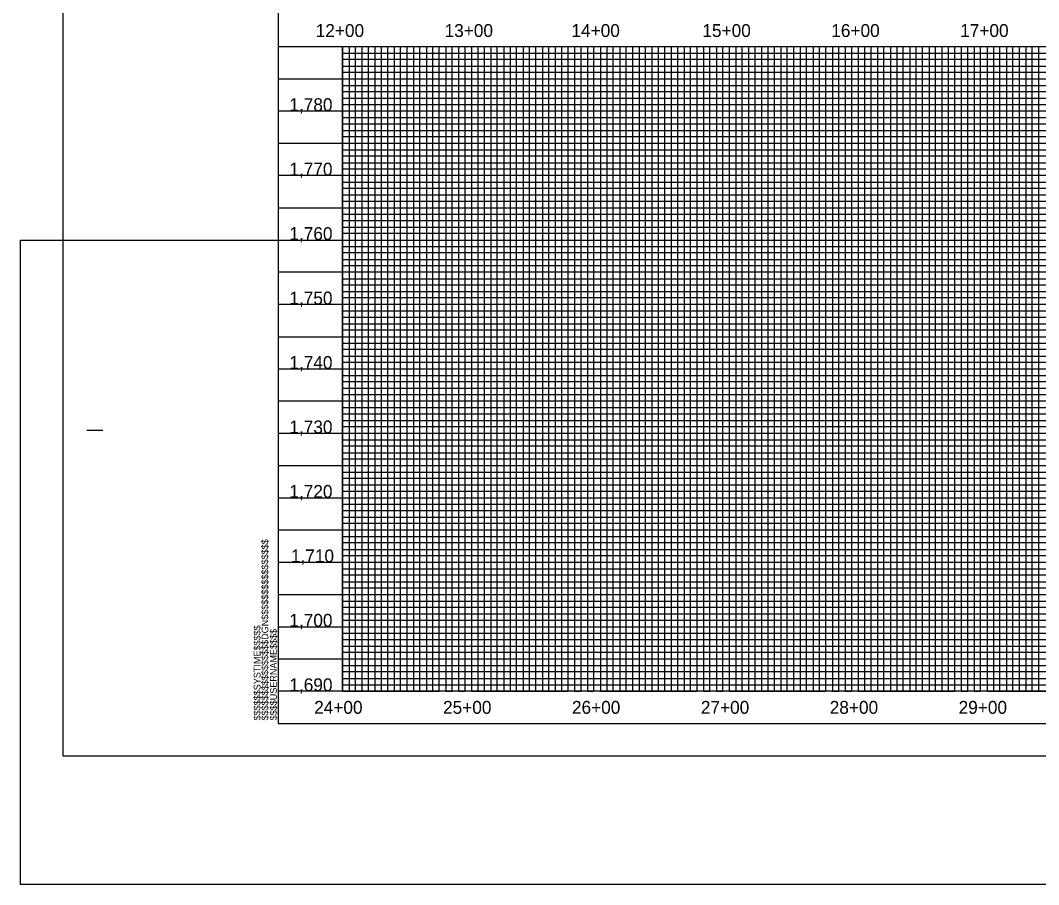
# Model space of a CAD drawing. Extents: x 505569 to 516904, y 436011 to 484484.
# Drawn here: x 505569 to 506359, y 483009 to 483679 of the extents above; entities that cross this region are included whole.
import ezdxf

# ---------------------------------------------------------------- set-up
doc = ezdxf.new("R2010")
doc.units = 0
for name, color, linetype in [('COGO Default Curve', 7, 'Continuous'), ('Exist Profile Cell', 7, 'Continuous'), ('Prop Grid Mask', 7, 'Continuous'), ('Prop Vertical Profile Curve Label', 7, 'Continuous'), ('Prop Vertical Profile Grade', 7, 'Continuous'), ('Prop Vertical Profile Grade Label', 7, 'Continuous'), ('Scratch_Level_2', 7, 'Continuous')]:
    doc.layers.add(name, color=color, linetype=linetype)

msp = doc.modelspace()

# ---------------------------------------------------------------- linework, layer by layer
at = {"layer": 'COGO Default Curve'}
for points in [[(505794.08, 483658.71), (505844.08, 483658.71), (505844.08, 483158.71), (505894.08, 483158.71), (505894.08, 483658.71), (505944.08, 483658.71), (505944.08, 483158.71), (505994.08, 483158.71), (505994.08, 483658.71), (506044.08, 483658.71), (506044.08, 483158.71), (506094.08, 483158.71), (506094.08, 483658.71), (506144.08, 483658.71), (506144.08, 483158.71), (506194.08, 483158.71), (506194.08, 483658.71), (506244.08, 483658.71), (506244.08, 483158.71), (506294.08, 483158.71), (506294.08, 483658.71), (506344.08, 483658.71), (506344.08, 483158.71), (506394.08, 483158.71)], [(505769.08, 483633.71), (507269.08, 483633.71)], [(507269.08, 483583.71), (505769.08, 483583.71), (505769.08, 483533.71), (507269.08, 483533.71)], [(507269.08, 483483.71), (505769.08, 483483.71), (505769.08, 483433.71), (507269.08, 483433.71)], [(507269.08, 483383.71), (505769.08, 483383.71), (505769.08, 483333.71), (507269.08, 483333.71)], [(507269.08, 483283.71), (505769.08, 483283.71), (505769.08, 483233.71), (507269.08, 483233.71)], [(507269.08, 483183.71), (505769.08, 483183.71)]]:
    msp.add_lwpolyline(points, dxfattribs=at)
at = {"layer": 'Prop Grid Mask'}
msp.add_lwpolyline([(505602.08, 483108.71), (507286.08, 483108.71), (507286.08, 484208.71), (505602.08, 484208.71)], close=True, dxfattribs=at)
at = {"layer": 'Prop Vertical Profile Curve Label'}
for p, q in [((505769.08, 483658.71), (507269.08, 483658.71)), ((505620.58, 483361.21), (505633.08, 483361.21)), ((507269.08, 483158.71), (505769.08, 483158.71)), ((505769.08, 483133.71), (507269.08, 483133.71)), ((505769.08, 483133.71), (505769.08, 483133.71)), ((505769.08, 483133.71), (505769.08, 483133.71)), ((505769.08, 483133.71), (505769.08, 483133.71)), ((505769.08, 483133.71), (505769.08, 483133.71)), ((505769.08, 483133.71), (505769.08, 483133.71)), ((505769.08, 483133.71), (505769.08, 483133.71)), ((505769.08, 483133.71), (505769.08, 483133.71))]:
    msp.add_line(p, q, dxfattribs=at)
msp.add_lwpolyline([(507269.08, 484183.71), (505769.08, 484183.71), (505769.08, 483133.71), (507269.08, 483133.71)], close=True, dxfattribs=at)
msp.add_lwpolyline([(505806.58, 483133.71), (505806.58, 483133.71)], dxfattribs=at)
at = {"layer": 'Prop Vertical Profile Grade'}
for points in [[(505819.08, 483658.71), (507219.08, 483658.71), (507219.08, 483158.71), (505819.08, 483158.71)], [(505569.08, 483508.71), (506969.08, 483508.71), (506969.08, 483008.71), (505569.08, 483008.71)]]:
    msp.add_lwpolyline(points, close=True, dxfattribs=at)
at = {"layer": 'Prop Vertical Profile Grade Label'}
for p, q in [((505819.08, 483653.71), (507219.08, 483653.71)), ((507219.08, 483648.71), (505819.08, 483648.71)), ((505819.08, 483643.71), (507219.08, 483643.71)), ((507219.08, 483638.71), (505819.08, 483638.71)), ((505819.08, 483628.71), (507219.08, 483628.71)), ((507219.08, 483623.71), (505819.08, 483623.71)), ((505819.08, 483618.71), (507219.08, 483618.71)), ((507219.08, 483613.71), (505819.08, 483613.71)), ((505819.08, 483603.71), (507219.08, 483603.71)), ((507219.08, 483598.71), (505819.08, 483598.71)), ((505819.08, 483593.71), (507219.08, 483593.71)), ((507219.08, 483588.71), (505819.08, 483588.71)), ((505819.08, 483578.71), (507219.08, 483578.71)), ((507219.08, 483573.71), (505819.08, 483573.71)), ((505819.08, 483568.71), (507219.08, 483568.71)), ((507219.08, 483563.71), (505819.08, 483563.71)), ((505819.08, 483553.71), (507219.08, 483553.71)), ((507219.08, 483548.71), (505819.08, 483548.71)), ((505819.08, 483543.71), (507219.08, 483543.71)), ((507219.08, 483538.71), (505819.08, 483538.71)), ((505819.08, 483528.71), (507219.08, 483528.71)), ((507219.08, 483523.71), (505819.08, 483523.71)), ((505819.08, 483518.71), (507219.08, 483518.71)), ((507219.08, 483513.71), (505819.08, 483513.71)), ((505819.08, 483503.71), (507219.08, 483503.71)), ((507219.08, 483498.71), (505819.08, 483498.71)), ((505819.08, 483493.71), (507219.08, 483493.71)), ((507219.08, 483488.71), (505819.08, 483488.71)), ((505819.08, 483478.71), (507219.08, 483478.71)), ((507219.08, 483473.71), (505819.08, 483473.71)), ((505819.08, 483468.71), (507219.08, 483468.71)), ((507219.08, 483463.71), (505819.08, 483463.86)), ((505819.08, 483453.71), (507219.08, 483453.71)), ((507219.08, 483448.71), (505819.08, 483448.71)), ((505819.08, 483443.71), (507219.08, 483443.71)), ((507219.08, 483438.71), (505819.08, 483438.71)), ((505819.08, 483428.71), (507219.08, 483428.71)), ((507219.08, 483423.71), (505819.08, 483423.71)), ((505819.08, 483418.71), (507219.08, 483418.71)), ((507219.08, 483413.71), (505819.08, 483413.71)), ((505819.08, 483403.71), (507219.08, 483403.71)), ((507219.08, 483398.71), (505819.08, 483398.71)), ((505819.08, 483393.71), (507219.08, 483393.71)), ((507219.08, 483388.71), (505819.08, 483388.71)), ((505819.08, 483378.71), (507219.08, 483378.71)), ((507219.08, 483373.71), (505819.08, 483373.71)), ((505819.08, 483368.71), (507219.08, 483368.71)), ((507219.08, 483363.71), (505819.08, 483363.71)), ((505819.08, 483353.71), (507219.08, 483353.71)), ((507219.08, 483348.71), (505819.08, 483348.71)), ((505819.08, 483343.71), (507219.08, 483343.71)), ((507219.08, 483338.71), (505819.08, 483338.71)), ((505819.08, 483328.71), (507219.08, 483328.71)), ((507219.08, 483323.71), (505819.08, 483323.71)), ((505819.08, 483318.71), (507219.08, 483318.71)), ((507219.08, 483313.71), (505819.08, 483313.71)), ((505819.08, 483303.71), (507219.08, 483303.71)), ((507219.08, 483298.71), (505819.08, 483298.71)), ((505819.08, 483293.71), (507219.08, 483293.71)), ((507219.08, 483288.71), (505819.08, 483288.71)), ((505819.08, 483278.71), (507219.08, 483278.71)), ((507219.08, 483273.71), (505819.08, 483273.71)), ((505819.08, 483268.71), (507219.08, 483268.71)), ((507219.08, 483263.71), (505819.08, 483263.71)), ((505819.08, 483253.71), (507219.08, 483253.71)), ((507219.08, 483248.71), (505819.08, 483248.71)), ((505819.08, 483243.71), (507219.08, 483243.71)), ((507219.08, 483238.71), (505819.08, 483238.71)), ((505819.08, 483228.71), (507219.08, 483228.71)), ((507219.08, 483223.71), (505819.08, 483223.71)), ((505819.08, 483218.71), (507219.08, 483218.71)), ((507219.08, 483213.71), (505819.08, 483213.71)), ((505819.08, 483203.71), (507219.08, 483203.71)), ((507219.08, 483198.71), (505819.08, 483198.71)), ((505819.08, 483193.71), (507219.08, 483193.71)), ((507219.08, 483188.71), (505819.08, 483188.71)), ((505819.08, 483178.71), (507219.08, 483178.71)), ((507219.08, 483173.71), (505819.08, 483173.71)), ((505819.08, 483168.71), (507219.08, 483168.71)), ((505819.08, 483163.71), (507219.08, 483163.71))]:
    msp.add_line(p, q, dxfattribs=at)
for points in [[(505819.08, 483658.71), (505824.08, 483658.71), (505824.08, 483158.71), (505829.08, 483158.71), (505829.08, 483658.71), (505834.08, 483658.71), (505834.08, 483158.71), (505839.08, 483158.71), (505839.08, 483658.71), (505849.08, 483658.71), (505849.08, 483158.71), (505854.08, 483158.71), (505854.08, 483658.71), (505859.08, 483658.71), (505859.08, 483158.71), (505864.08, 483158.71), (505874.08, 483158.71), (505879.08, 483158.71), (505879.08, 483658.71), (505884.08, 483658.71), (505884.08, 483158.71), (505889.08, 483158.71), (505889.08, 483658.71), (505899.08, 483658.71), (505899.08, 483158.71), (505904.08, 483158.71), (505904.08, 483658.71), (505909.08, 483658.71), (505909.08, 483158.71), (505914.08, 483158.71), (505914.08, 483658.71), (505924.08, 483658.71), (505924.08, 483158.71), (505929.08, 483158.71), (505929.08, 483658.71), (505934.08, 483658.71), (505934.08, 483158.71), (505939.08, 483158.71), (505939.08, 483658.71), (505949.08, 483658.71), (505949.08, 483158.71), (505954.08, 483158.71), (505954.08, 483658.71), (505959.08, 483658.71), (505959.08, 483158.71), (505964.08, 483158.71), (505964.08, 483658.71), (505974.08, 483658.71), (505974.08, 483158.71), (505979.08, 483158.71), (505979.08, 483658.71), (505984.08, 483658.71), (505984.08, 483158.71), (505989.08, 483158.71), (505989.08, 483658.71), (505999.08, 483658.71), (505999.08, 483158.71), (506004.08, 483158.71), (506004.08, 483658.71), (506009.08, 483658.71), (506009.08, 483158.71), (506014.08, 483158.71), (506014.08, 483658.71), (506024.08, 483658.71), (506024.08, 483158.71), (506029.08, 483158.71), (506029.08, 483658.71), (506034.08, 483658.71), (506034.08, 483158.71)], [(505864.08, 483158.71), (505864.08, 483658.71), (505874.08, 483658.71), (505874.08, 483158.71)], [(506034.08, 483158.71), (506039.08, 483158.71), (506039.08, 483658.71), (506049.08, 483658.71), (506049.08, 483158.71), (506054.08, 483158.71), (506054.08, 483658.71), (506059.08, 483658.71), (506059.08, 483158.71), (506064.08, 483158.71), (506064.08, 483658.71), (506074.08, 483658.71), (506074.08, 483158.71), (506079.08, 483158.71), (506079.08, 483658.71), (506084.08, 483658.71), (506084.08, 483158.71), (506089.08, 483158.71), (506089.08, 483658.71), (506099.08, 483658.71), (506099.08, 483158.71), (506104.08, 483158.71), (506104.08, 483658.71), (506109.08, 483658.71), (506109.08, 483158.71), (506114.08, 483158.71), (506114.08, 483658.71), (506124.08, 483658.71), (506124.08, 483158.71), (506129.08, 483158.71), (506129.08, 483658.71), (506134.08, 483658.71), (506134.08, 483158.71), (506139.08, 483158.71), (506139.08, 483658.71), (506149.08, 483658.71), (506149.08, 483158.71), (506154.08, 483158.71), (506154.08, 483658.71), (506159.08, 483658.71), (506159.08, 483158.71), (506164.08, 483158.71), (506164.08, 483658.71), (506174.08, 483658.71), (506174.08, 483158.71), (506179.08, 483158.71), (506179.08, 483658.71), (506184.08, 483658.71), (506184.08, 483158.71), (506189.08, 483158.71), (506189.08, 483658.71), (506199.08, 483658.71), (506199.08, 483158.71), (506204.08, 483158.71), (506204.08, 483658.71), (506209.08, 483658.71), (506209.08, 483158.71), (506214.08, 483158.71), (506214.08, 483658.71), (506224.08, 483658.71), (506224.08, 483158.71), (506229.08, 483158.71), (506229.08, 483658.71), (506234.08, 483658.71), (506234.08, 483158.71), (506239.08, 483158.71), (506239.08, 483658.71), (506249.08, 483658.71), (506249.08, 483158.71), (506254.08, 483158.71), (506254.08, 483658.71), (506259.08, 483658.71), (506259.08, 483158.71), (506264.08, 483158.71), (506264.08, 483658.71), (506274.08, 483658.71), (506274.08, 483158.71), (506279.08, 483158.71), (506279.08, 483658.71), (506284.08, 483658.71), (506284.08, 483158.71), (506289.08, 483158.71), (506289.08, 483658.71), (506299.08, 483658.71), (506299.08, 483158.71), (506304.08, 483158.71), (506304.08, 483658.71), (506309.08, 483658.71), (506309.08, 483158.71), (506314.08, 483158.71), (506314.08, 483658.71), (506324.08, 483658.71), (506324.08, 483158.71), (506329.08, 483158.71), (506329.08, 483658.71), (506334.08, 483658.71), (506334.08, 483158.71), (506339.08, 483158.71), (506339.08, 483658.71), (506349.08, 483658.71)], [(506349.08, 483658.71), (506349.08, 483158.71), (506354.08, 483158.71), (506354.08, 483658.71), (506359.08, 483658.71), (506359.08, 483158.71), (506364.08, 483158.71)]]:
    msp.add_lwpolyline(points, dxfattribs=at)
at = {"layer": 'Scratch_Level_2'}
msp.add_line((506269.08, 483658.71), (506319.08, 483658.71), dxfattribs=at)
for points in [[(505819.08, 483658.71), (505819.08, 483158.71), (505869.08, 483158.71), (505869.08, 483658.71), (505919.08, 483658.71), (505919.08, 483158.71), (505969.08, 483158.71), (505969.08, 483658.71), (506019.08, 483658.71), (506019.08, 483158.71), (506069.08, 483158.71), (506069.08, 483658.71), (506119.08, 483658.71), (506119.08, 483158.71), (506169.08, 483158.71), (506169.08, 483658.71), (506219.08, 483658.71), (506219.08, 483158.71), (506269.08, 483158.71), (506269.08, 483658.71), (506319.08, 483658.71), (506319.08, 483158.71), (506369.08, 483158.71)], [(505819.08, 483658.71), (505819.08, 483158.71), (505869.08, 483158.71), (505869.08, 483658.71), (505919.08, 483658.71), (505919.08, 483158.71), (505969.08, 483158.71), (505969.08, 483658.71), (506019.08, 483658.71), (506019.08, 483158.71), (506069.08, 483158.71), (506069.08, 483658.71), (506119.08, 483658.71), (506119.08, 483158.71), (506169.08, 483158.71), (506169.08, 483658.71), (506219.08, 483658.71), (506219.08, 483158.71), (506269.08, 483158.71), (506269.08, 483658.71), (506319.08, 483658.71), (506319.08, 483158.71), (506369.08, 483158.71)], [(507269.08, 483608.71), (505769.08, 483608.71)], [(507269.08, 483558.71), (505769.08, 483558.71), (505769.08, 483508.71), (507269.08, 483508.71)], [(507269.08, 483458.71), (505769.08, 483458.71), (505769.08, 483408.71), (507269.08, 483408.71)], [(507269.08, 483358.71), (505769.08, 483358.71), (505769.08, 483308.71), (507269.08, 483308.71)], [(507269.08, 483258.71), (505769.08, 483258.71), (505769.08, 483258.71), (505769.08, 483208.71), (507269.08, 483208.71)], [(507269.08, 483158.71), (505769.08, 483158.71)]]:
    msp.add_lwpolyline(points, dxfattribs=at)

# ---------------------------------------------------------------- texts
at = {"layer": 'Exist Profile Cell'}
for s, p in [('12+00', (505798.21, 483666.21)), ('13+00', (505898.21, 483666.21)), ('14+00', (505996.63, 483666.21)), ('15+00', (506098.21, 483666.21)), ('16+00', (506198.21, 483666.21)), ('17+00', (506298.21, 483666.21)), ('1,780', (505777.78, 483608.71)), ('1,770', (505777.78, 483558.71)), ('1,760', (505777.78, 483508.71)), ('1,750', (505777.78, 483458.71)), ('1,740', (505777.78, 483408.71)), ('1,730', (505777.78, 483358.71)), ('1,720', (505777.78, 483308.71)), ('1,710', (505778.97, 483258.71)), ('1,700', (505777.78, 483208.71)), ('1,690', (505777.78, 483158.71)), ('24+00', (505797.01, 483141.21)), ('25+00', (505897.01, 483141.21)), ('26+00', (505997.01, 483141.21)), ('27+00', (506097.01, 483141.21)), ('28+00', (506197.01, 483141.21)), ('29+00', (506297.01, 483141.21))]:
    msp.add_text(s, height=10, dxfattribs=at).set_placement(p)
at = {"layer": 'Prop Vertical Profile Curve Label'}
for s, p in [('$$$$$$$$$$$$$$$$DGN$$$$$$$$$$$$$$$$', (505761.44, 483136.09)), ('$$$$$$SYSTIME$$$$$', (505755.39, 483136.09)), ('$$$$USERNAME$$$$', (505768.02, 483136.1))]:
    msp.add_text(s, height=5.25, rotation=90, dxfattribs=at).set_placement(p)

doc.saveas('drawing.dxf')
